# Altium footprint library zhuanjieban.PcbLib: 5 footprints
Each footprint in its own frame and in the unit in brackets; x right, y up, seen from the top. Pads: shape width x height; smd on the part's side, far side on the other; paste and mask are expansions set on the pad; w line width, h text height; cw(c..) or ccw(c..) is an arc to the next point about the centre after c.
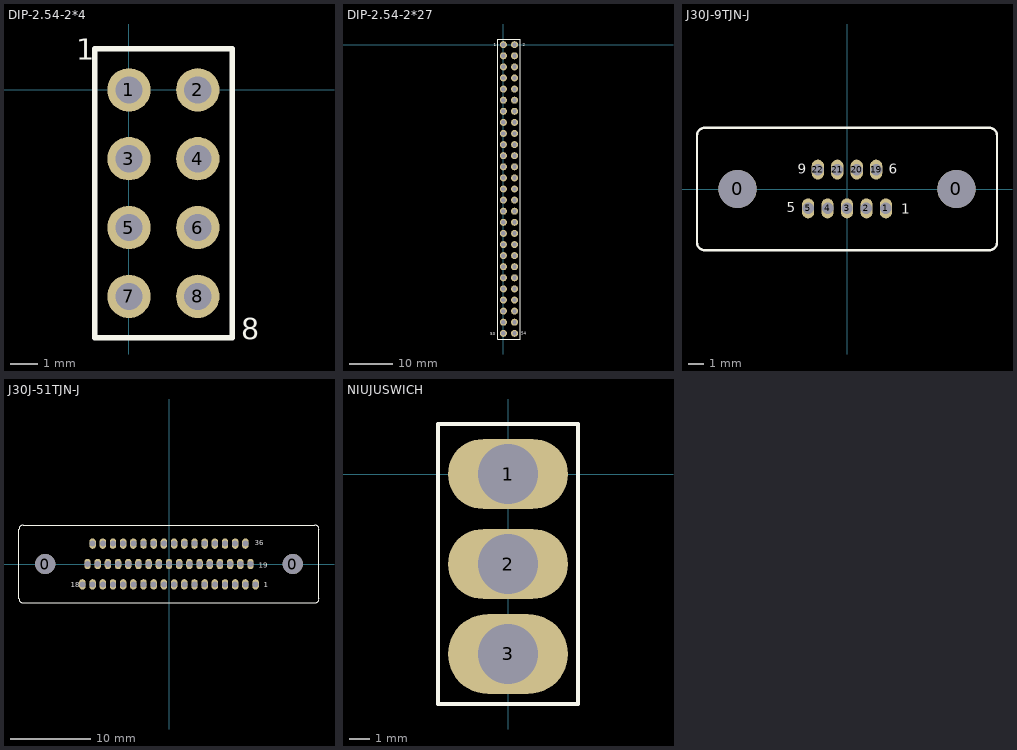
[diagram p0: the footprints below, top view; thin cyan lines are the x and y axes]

## DIP-2.54-2*4 [mm]
pads (8):
  round 1.6 hole 1: 1(0,0) 2(2.54,0) 3(0,-2.54) 4(2.54,-2.54) 5(0,-5.08) 6(2.54,-5.08) 7(0,-7.62) 8(2.54,-7.62)
Top Overlay:
  lines w0.203: -1.27,-9.144 3.81,-9.144 3.81,1.524 -1.27,1.524 -1.27,-9.144
  text "1" at -1.951,1.117 h0.76
  text "8" at 4.145,-9.195 h0.76

## DIP-2.54-2*27 [mm]
pads (54):
  round 1.6 hole 1: 1(0,0) 2(2.54,0) 3(0,-2.54) 4(2.54,-2.54) 5(0,-5.08) 6(2.54,-5.08) 7(0,-7.62) 8(2.54,-7.62) 9(0,-10.16) 10(2.54,-10.16) 11(0,-12.7) 12(2.54,-12.7) 13(0,-15.24) 14(2.54,-15.24) 15(0,-17.78) 16(2.54,-17.78) 17(0,-20.32) 18(2.54,-20.32) 19(0,-22.86) 20(2.54,-22.86) 21(0,-25.4) 22(2.54,-25.4) 23(0,-27.94) 24(2.54,-27.94) 25(0,-30.48) 26(2.54,-30.48) 27(0,-33.02) 28(2.54,-33.02) 29(0,-35.56) 30(2.54,-35.56) 31(0,-38.1) 32(2.54,-38.1) 33(0,-40.64) 34(2.54,-40.64) 35(0,-43.18) 36(2.54,-43.18) 37(0,-45.72) 38(2.54,-45.72) 39(0,-48.26) 40(2.54,-48.26) 41(0,-50.8) 42(2.54,-50.8) 43(0,-53.34) 44(2.54,-53.34) 45(0,-55.88) 46(2.54,-55.88) 47(0,-58.42) 48(2.54,-58.42) 49(0,-60.96) 50(2.54,-60.96) 51(0,-63.5) 52(2.54,-63.5) 53(0,-66.04) 54(2.54,-66.04)
Top Overlay:
  lines w0.15: -1.3,-67.34 -1.3,1.3 3.84,1.3 3.84,-67.34 -1.3,-67.34
  text "1" at -2.178,-0.344 h0.64
  text "2" at 4.426,-0.344 h0.64
  text "54" at 4.04,-66.39 h0.64
  text "53" at -2.96,-66.44 h0.64

## J30J-9TJN-J [mm]
pads (11):
  round 2.5 hole 2.5: 0(-7.15,0) 0(7.15,0)
  oval 0.8x1.3 hole 0.75: 1(2.54,-1.27) 2(1.27,-1.27) 3(0,-1.27) 4(-1.27,-1.27) 5(-2.54,-1.27) 19(1.905,1.27) 20(0.635,1.27) 21(-0.635,1.27) 22(-1.905,1.27)
Top Overlay:
  lines w0.152: -9.8,-3.5 ccw(c-9.3,-3.5) -9.3,-4 -3,-4 3.84,-4 9.3,-4 ccw(c9.3,-3.5) 9.8,-3.5 9.8,-1.81 9.8,2.9 9.8,3.5 ccw(c9.3,3.5) 9.3,4 3.84,4 -2.9,4 -9.3,4 ccw(c-9.3,3.5) -9.8,3.5 -9.8,2.8 -9.8,-1.81 -9.8,-3.5
  text "6" at 2.743,0.991 h0.64
  text "9" at -3.226,0.991 h0.64
  text "5" at -3.937,-1.524 h0.64
  text "1" at 3.556,-1.626 h0.64

## J30J-51TJN-J [mm]
pads (53):
  round 2.5 hole 2.5: 0(-15.43,0) 0(15.43,0)
  oval 0.8x1.3 hole 0.75: 1(10.795,-2.54) 2(9.525,-2.54) 3(8.255,-2.54) 4(6.985,-2.54) 5(5.715,-2.54) 6(4.445,-2.54) 7(3.175,-2.54) 8(1.905,-2.54) 9(0.635,-2.54) 10(-0.635,-2.54) 11(-1.905,-2.54) 12(-3.175,-2.54) 13(-4.445,-2.54) 14(-5.715,-2.54) 15(-6.985,-2.54) 16(-8.255,-2.54) 17(-9.525,-2.54) 18(-10.795,-2.54) 19(10.16,0) 20(8.89,0) 21(7.62,0) 22(6.35,0) 23(5.08,0) 24(3.81,0) 25(2.54,0) 26(1.27,0) 27(0,0) 28(-1.27,0) 29(-2.54,0) 30(-3.81,0) 31(-5.08,0) 32(-6.35,0) 33(-7.62,0) 34(-8.89,0) 35(-10.16,0) 36(9.525,2.54) 37(8.255,2.54) 38(6.985,2.54) 39(5.715,2.54) 40(4.445,2.54) 41(3.175,2.54) 42(1.905,2.54) 43(0.635,2.54) 44(-0.635,2.54) 45(-1.905,2.54) 46(-3.175,2.54) 47(-4.445,2.54) 48(-5.715,2.54) 49(-6.985,2.54) 50(-8.255,2.54) 51(-9.525,2.54)
Top Overlay:
  lines w0.152: -18.7,-4.35 ccw(c-18.2,-4.35) -18.2,-4.85 -12.7,-4.85 12.095,-4.85 18.2,-4.85 ccw(c18.2,-4.35) 18.7,-4.35 18.7,4.35 ccw(c18.2,4.35) 18.2,4.85 12.095,4.85 -12.7,4.85 -18.2,4.85 ccw(c-18.2,4.35) -18.7,4.35 -18.7,-4.35
  text "19" at 11.201,-0.483 h0.64
  text "36" at 10.668,2.311 h0.64
  text "18" at -12.217,-2.87 h0.64
  text "1" at 11.836,-2.921 h0.64

## NIUJUSWICH [mm]
pads (3):
  oval 6x3.5 hole 3: 1(0,0) 2(0,-4.5)
  oval 6x4 hole 3: 3(0,-9)
Top Overlay:
  lines w0.203: -3.5,-11.5 -3.5,2.5 3.5,2.5 3.5,-11.5 -3.5,-11.5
